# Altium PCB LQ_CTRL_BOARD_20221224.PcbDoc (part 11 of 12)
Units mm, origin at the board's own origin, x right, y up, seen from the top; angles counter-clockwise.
Board outline 260 x 142 mm, 6 copper layers (Top Layer, Mid-Layer 1, Mid-Layer 2, Mid-Layer 3, Mid-Layer 4, Bottom Layer); 1105 components, 1039 nets, 3898 pads, 1277 vias.
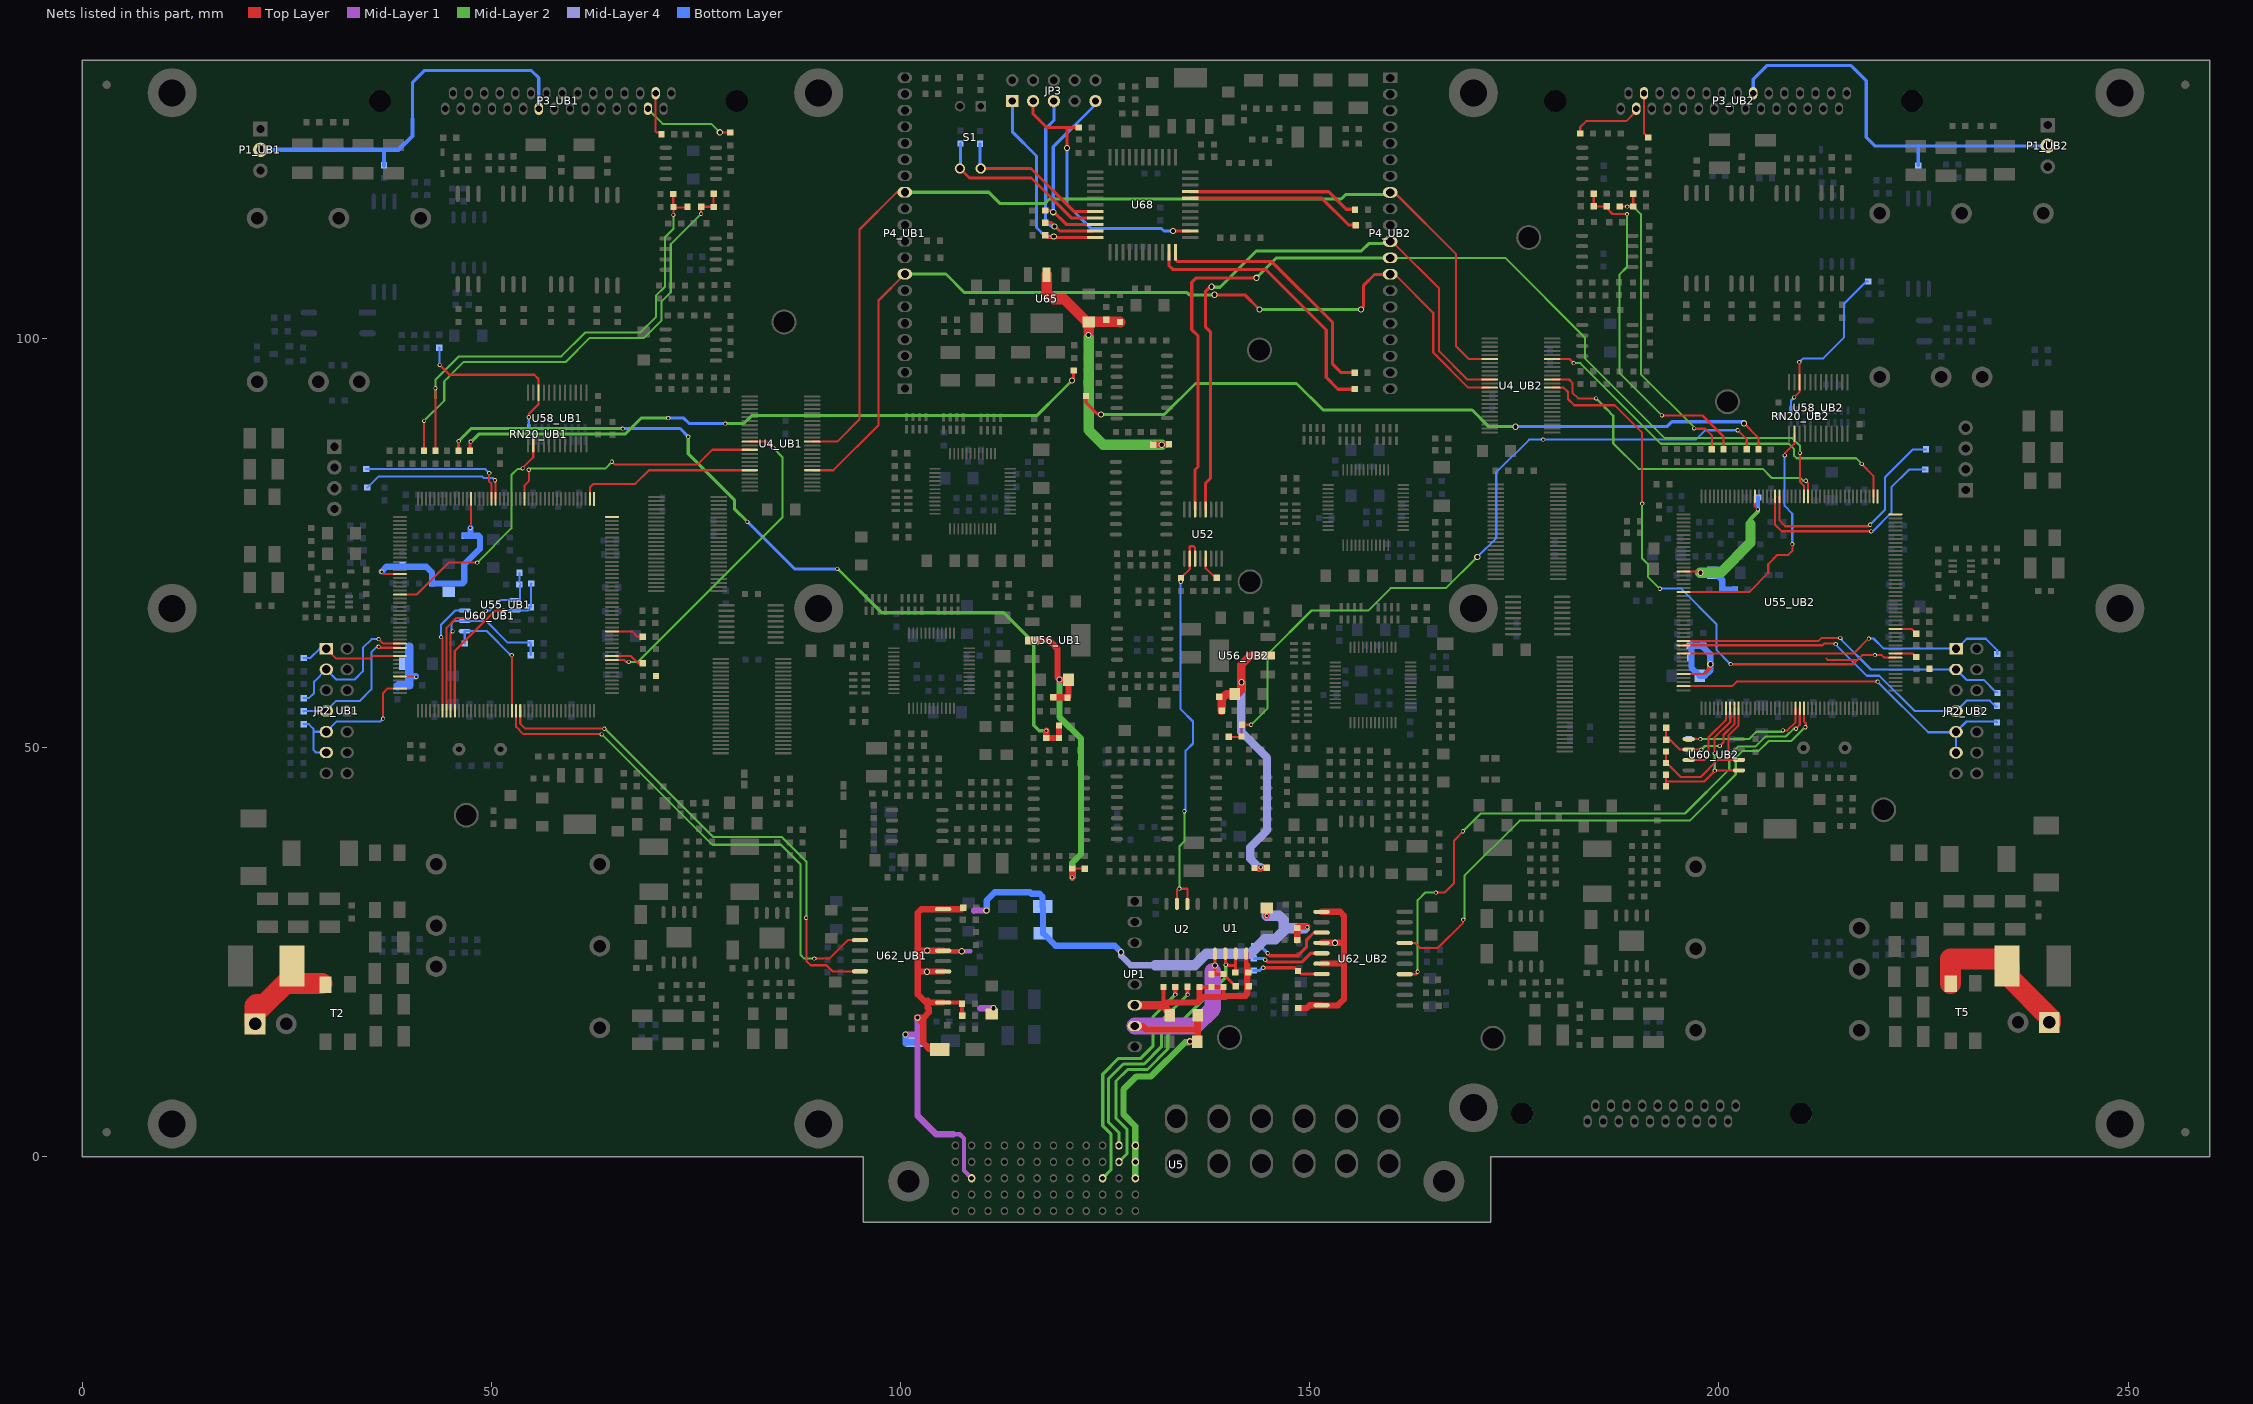
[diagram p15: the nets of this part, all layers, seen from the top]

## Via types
v1: diameter 0.508, hole 0.305, Top Layer to Bottom Layer, 845 vias
v2: diameter 0.762, hole 0.508, Top Layer to Bottom Layer, 317 vias
v3: diameter 1.27, hole 0.762, Top Layer to Bottom Layer, 77 vias
v4: diameter 2.032, hole 1.524, Top Layer to Bottom Layer, 15 vias
v5: diameter 2.032, hole 1.27, Top Layer to Bottom Layer, 11 vias
v6: diameter 1.27, hole 0.711, Top Layer to Bottom Layer, 8 vias
v7: diameter 2.54, hole 1.778, Top Layer to Bottom Layer, 3 vias
v8: diameter 1.524, hole 1.016, Top Layer to Bottom Layer, 1 vias

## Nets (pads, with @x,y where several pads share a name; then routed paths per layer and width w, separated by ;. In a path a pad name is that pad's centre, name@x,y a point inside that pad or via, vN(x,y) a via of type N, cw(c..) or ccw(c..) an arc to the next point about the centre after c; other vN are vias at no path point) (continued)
RS422_B_UB2: R366_UB2.1 R422.2 U62_UB2.17 | length 8.9
  Top Layer w0.381: v1(144.323,23.089) 148.172,23.089 R366_UB2.1@148.579,22.682 148.934,22.327 U62_UB2.17@151.455,22.327
  Bottom Layer w0.381: R422.2@143.154,22.758 143.916,22.758 144.323,23.165 v1(144.323,23.089)
RS422_GND_UB1: C420_UB1.2 C420_UB2.2 C421_UB1.2 C421_UB2.2 C422_UB1.2 C422_UB2.2 DR5.1 DR6.1 DR7.1 DR8.1 R365_UB1.1 R365_UB2.1 U5.C2 U62_UB1.11 U62_UB1.14 U62_UB1.16 U62_UB1.20 U62_UB2.11 U62_UB2.14 U62_UB2.16 U62_UB2.20 | length 160.3
  Top Layer w0.381: U62_UB1.16@105.276,25.108 v2(107.493,25.108)
  Top Layer w0.508: U62_UB1.11@105.212,18.847 107.366,18.847 C422_UB1.2@107.518,18.694 C421_UB1.2@107.518,17.221
  Top Layer w0.762: 102.337,22.631 U62_UB1.14@105.212,22.631 ; 102.514,25.171 U62_UB1.16@105.212,25.171 ; 103.238,13.475 102.819,13.894 ; DR7.1@104.8,13.106 103.607,13.106 102.819,13.894 ; U62_UB1.11@105.212,18.847 103.53,18.847 103.327,19.05 103.327,18.618 ; R365_UB1.1@107.676,30.429 107.498,30.251 U62_UB1.20@105.212,30.251 102.54,30.251 102.108,29.82 102.108,19.837 103.327,18.618 ; v2(111.379,18.136) 111.379,17.17 C420_UB1.2@111.392,17.183 ; v1(144.729,29.439) C420_UB2.2@144.729,30.404 ; C422_UB2.2@148.488,26.354 C422_UB2.2@148.488,26.492 C421_UB2.2@148.488,27.936 148.488,28.042 148.59,28.143 v1@149.708,28.143 ; R365_UB2.1@148.604,18.161 149.657,18.161 150.012,18.517 U62_UB2.20@151.455,18.517 151.48,18.491 153.416,18.491 154.178,19.253 154.178,23.571 ; U62_UB2.16@151.455,23.597 154.153,23.597 154.178,23.571 ; U62_UB2.14@151.455,26.137 v2(153.086,26.137) ; U62_UB2.11@151.455,29.921 153.721,29.921 154.178,29.464 154.178,26.238 ; v2@153.111,26.137 v2(153.086,26.137) ; 102.819,13.894 102.819,16.993 ; 102.819,13.894 102.794,13.919 102.794,16.231 102.032,16.993 v2(102.083,16.993) 102.819,16.993 ; 102.819,16.993 103.454,17.628 103.454,18.085 103.327,18.212 103.327,18.618 ; v2(153.086,26.137) 154.076,26.137 154.178,26.238 ; 154.178,23.571 154.178,26.238
  Mid-Layer 1 w0.508: 105.054,25.019 105.131,25.095 107.48,25.095 v2(107.493,25.108) 108.547,25.108 108.56,25.121 ; 106.451,2.743 107.239,2.743 107.772,2.21 107.772,-1.699 U5.C2@108.7,-2.627
  Mid-Layer 1 w0.762: v2(100.609,14.935) 101.956,14.935 ; 102.032,13.665 102.083,13.716 ; v2@102.032,16.993 v2@102.083,16.942 ; v2(102.083,16.993) v2@102.083,16.942 ; 106.451,2.743 104.343,2.743 102.083,5.004 102.083,13.716 ; 108.991,30.048 109.042,30.099 v2(110.49,30.099) ; 109.753,18.11 109.779,18.136 v2(111.379,18.136) ; 102.083,13.716 v2@102.083,16.942
  Mid-Layer 4 w0.762: v2(126.949,24.994) 126.949,24.562 128.118,23.393 131.14,23.393
  Mid-Layer 4 w1.27: 131.14,23.393 135.941,23.393 137.338,24.79 142.748,24.79 144.526,26.568 145.796,26.568 146.812,27.584 146.812,27.936 ; v1(144.729,29.439) 146.253,29.439 146.812,28.88 146.812,27.936 ; 149.377,27.936 146.812,27.936
  Bottom Layer w0.762: v2(100.609,14.935) 100.609,13.843 100.762,13.995 DR5.1@101.803,13.995 ; v2@110.541,30.099 110.541,31.318 111.531,32.309 115.824,32.309 116.002,32.131 116.992,32.131 117.348,31.775 117.348,30.607 DR6.1@117.373,30.582 117.424,30.531 DR8.1@117.424,27.305 118.948,25.781 126.187,25.781 v2@127,24.968
  other v1: 149.733,28.042
  other v2: 103.226,22.606 103.276,25.197
RS422_Y_UB2: R424.2 U62_UB2.13 | length 10.2
  Top Layer w0.381: v1@144.856,24.79 145.085,24.562 148.539,24.562 149.631,25.654 149.631,26.518 150.52,27.407 U62_UB2.13@151.455,27.407
  Bottom Layer w0.381: R424.2@143.205,25.73 143.993,25.73 v1@144.755,24.968
  other v1: 144.856,24.867
RS422_Z_UB2: R423.2 U62_UB2.15 | length 8.8
  Top Layer w0.381: v1(144.577,24.054) 144.831,23.8 149.073,23.8 149.327,24.054 150.139,24.867 U62_UB2.15@151.455,24.867
  Bottom Layer w0.381: R423.2@143.18,24.232 v1@144.577,24.232
S_EXT_IO_IN1: R432.2 U68.22 | length 31.6
  Top Layer w0.381: U68.22@133.6,110.52 133.6,109.631 133.858,109.372 145.364,109.372 152.806,101.93 152.806,96.85 153.848,95.809 155.27,95.809 R432.2@155.499,95.58
S_EXT_IO_IN2: R433.2 U68.21 | length 33.7
  Top Layer w0.381: U68.21@132.8,110.52 132.8,108.907 133.274,108.433 144.602,108.433 152.019,101.016 152.019,95.225 153.467,93.777 R433.2@155.245,93.777
S_EXT_IO_OUT1: R434.2 U68.30 | length 21.1
  Top Layer w0.381: U68.30@135.4,117.907 152.298,117.907 152.311,117.919 154.457,115.773 155.346,115.773 R434.2@155.55,115.57
S_EXT_IO_OUT2: R436.2 U68.29 | length 21.7
  Top Layer w0.381: U68.29@135.4,117.12 151.485,117.12 154.762,113.843 155.397,113.843 R436.2@155.626,113.614
S_SYN_CLK: P4_UB2.11 U4_UB2.11 U52.4 | length 76.4
  Top Layer w0.254: P4_UB2.11@159.842,111.572 160.335,111.572 165.811,106.096 165.811,98.425 169.262,94.974 U4_UB2.11@172.72,94.974
  Top Layer w0.381: U52.4@137.293,79.087 137.293,82.327 137.897,82.931 137.897,100.762 137.293,101.366 137.293,105.771 137.77,106.248 v2@138.024,106.248
  Mid-Layer 2 w0.381: v2(138.024,106.299) 138.074,106.248 139.04,106.248 143.459,110.668 156.312,110.668 157.216,111.572 P4_UB2.11@159.842,111.572
S_SYN_CLKIN: P4_UB2.12 U52.6 U55_UB2.19 | length 121.4
  Top Layer w0.254: v2@143.434,107.315 v2(143.51,107.391) ; P4_UB2.12@159.635,109.572 P4_UB2.12@159.842,109.572 ; v1(209.906,86.004) 209.911,85.999 209.911,82.468 210.385,81.994 U55_UB2.19@210.385,80.696
  Top Layer w0.381: U52.6@135.993,79.087 135.993,83.923 136.347,84.277 136.347,100.305 135.585,101.067 135.585,106.858 136.119,107.391 143.358,107.391 v2@143.434,107.315
  Mid-Layer 2 w0.254: P4_UB2.12@159.585,109.83 173.888,109.83 183.617,100.101 183.617,97.561 193.37,87.808 208.966,87.808 209.911,86.863 209.911,86.007 209.908,86.004 v1(209.906,86.004)
  Mid-Layer 2 w0.381: v2(143.51,107.391) 145.948,109.83 P4_UB2.12@159.585,109.83
S_SYNC_CLK: R6.1 U52.13 | length 3
  Top Layer w0.254: U52.13@137.293,73.087 137.293,71.902 138.455,70.739 R6.1@138.659,70.739
SCI_RXDA_UB1: U4_UB1.36 U55_UB1.141 | length 40.4
  Top Layer w0.254: U55_UB1.141@64.74,60.691 66.258,60.691 66.497,60.452 v1(66.802,60.452) ; U4_UB1.36@81.585,87.382 83.687,87.382 v1(84.455,86.614)
  Mid-Layer 2 w0.254: v1(66.802,60.452) 67.92,60.452 85.573,78.105 85.573,85.496 v1(84.455,86.614)
SCI_RXDA_UB2: U4_UB2.36 U55_UB2.141 | length 72.7
  Top Layer w0.254: U4_UB2.36@179.629,93.974 180.981,93.974 181.077,93.878 181.127,93.878 181.559,93.447 181.559,92.583 182.321,91.821 187.257,91.821 190.627,88.451 v1(190.627,79.807) ; v1@201.422,60.173 216.398,60.173 216.916,60.691 ; 213.157,60.858 213.324,60.691 216.916,60.691 ; U55_UB2.141@221.585,60.996 220.208,60.996 219.913,61.29 v1(219.075,61.29) 217.515,61.29 216.916,60.691
  Mid-Layer 2 w0.254: v1(190.627,79.807) 190.627,73.101 191.364,72.365 191.364,70.815 v1(192.786,69.393)
  Bottom Layer w0.254: v1(192.786,69.393) 192.786,69.418 192.811,69.444 195.351,69.444 199.695,65.1 199.695,61.925 v1(201.422,60.198)
SCI_TXDA_UB1: U4_UB1.43 U55_UB1.2 | length 22.5
  Top Layer w0.254: U55_UB1.2@62.04,80.391 62.04,81.776 62.484,82.22 67.615,82.22 69.277,83.882 U4_UB1.43@82.321,83.882
SCI_TXDA_UB2: U4_UB2.43 U55_UB2.2 | length 48.2
  Top Layer w0.254: U4_UB2.43@179.629,97.474 181.748,97.474 v1(182.245,96.977) ; v1@217.424,84.658 218.885,83.197 U55_UB2.2@218.885,80.696
  Mid-Layer 2 w0.254: v1(182.245,96.977) 183.058,96.977 192.913,87.122 208.534,87.122 209.194,86.462 209.194,85.649 209.499,85.344 216.764,85.344 v1(217.449,84.658)
SCIRXDA_UB1: P4_UB1.13 P4_UB2.8 U4_UB1.13 U4_UB2.6 | length 125.7
  Top Layer w0.254: U4_UB1.13@89.205,87.382 92.258,87.382 94.996,90.119 94.996,113.295 99.554,117.853 P4_UB1.13@100.533,117.853 ; P4_UB2.8@159.842,117.572 160.609,117.572 167.869,110.312 167.869,99.06 169.454,97.474 U4_UB2.6@172.72,97.474
  Mid-Layer 2 w0.381: P4_UB1.13@100.533,117.853 110.798,117.853 112.192,116.459 117.653,116.459 118.212,117.018 153.848,117.018 154.402,117.572 P4_UB2.8@159.842,117.572
SCIRXDA_UB2: P4_UB1.8 P4_UB2.13 U4_UB1.6 U4_UB2.13 | length 115.7
  Top Layer w0.254: U4_UB1.6@89.205,83.882 91.806,83.882 97.307,89.383 97.307,104.627 P4_UB1.8@100.533,107.853 ; P4_UB2.13@159.842,107.572 160.627,107.572 165.1,103.099 165.1,98.273 169.398,93.974 U4_UB2.13@172.009,93.974
  Top Layer w0.381: v2@138.379,105.308 142.088,105.308 v2(143.866,103.53) ; 156.591,103.835 156.591,106.477 157.912,107.798 159.617,107.798 P4_UB2.13@159.842,107.572
  Mid-Layer 2 w0.381: P4_UB1.8@100.533,107.853 105.558,107.853 107.823,105.588 135.026,105.588 135.306,105.308 135.509,105.308 138.354,105.308 v2(138.379,105.334) ; v2(143.866,103.53) v2(156.286,103.53) 155.524,103.53
SCIRXDB_UB1: R29_UB1.1 U55_UB1.26 | length 18.5
  Top Layer w0.254: v1(49.759,83.541) 49.714,83.496 49.714,82.53 50.04,82.204 U55_UB1.26@50.04,80.391
  Bottom Layer w0.254: R29_UB1.1@34.722,84.023 47.396,84.023 49.276,84.023 v1(49.759,83.541)
SCIRXDB_UB2: R29_UB2.1 U55_UB2.26 | length 27.2
  Top Layer w0.254: U55_UB2.26@206.885,80.696 206.844,80.654 206.844,77.255 207.67,76.429 218.567,76.429 v1(218.592,76.403)
  Bottom Layer w0.254: v1(218.592,76.403) 218.794,76.403 221.082,78.691 221.082,81.813 223.241,83.972 224.003,83.972 R29_UB2.1@225.222,83.972
SCIRXDC_UB1: U55_UB1.113 U62_UB1.4 | length 63.1
  Top Layer w0.254: U55_UB1.113@53.04,54.491 53.04,52.522 53.924,51.638 63.449,51.638 v1(63.475,51.613) ; v1(89.459,24.206) 91.303,24.206 93.563,26.467 U62_UB1.4@95.052,26.467
  Mid-Layer 2 w0.254: v1@63.5,51.638 77.013,38.125 85.395,38.125 87.782,35.738 87.782,24.689 88.265,24.206 v1(89.459,24.206)
SCIRXDC_UB2: U55_UB2.113 U62_UB2.4 | length 72.4
  Top Layer w0.254: U62_UB2.4@161.615,22.301 163.017,22.301 v1@163.246,22.53 ; v1(165.43,32.283) 166.522,32.283 167.64,33.401 167.64,38.633 168.758,39.751 v1(168.732,39.776) ; v1(209.423,52.299) 209.885,52.761 ; 209.885,53.035 209.885,52.761 ; U55_UB2.113@209.885,54.796 209.885,52.761
  Mid-Layer 2 w0.254: v1(163.195,22.606) 163.195,31.344 164.135,32.283 v1(165.43,32.283) ; v1@168.732,39.751 170.917,41.935 195.859,41.935 201.27,47.346 201.27,49.022 202.387,50.14 204.495,50.14 205.715,51.359 208.204,51.359 209.144,52.299 v1(209.423,52.299)
SCITXDB_UB1: R30_UB1.2 U55_UB1.25 | length 18.6
  Top Layer w0.254: v1(50.444,82.652) 50.54,82.556 U55_UB1.25@50.54,80.391
  Bottom Layer w0.254: R30_UB1.2@34.849,81.763 36.195,83.109 48.895,83.109 49.073,82.931 50.165,82.931 v1(50.444,82.652)
SCITXDB_UB2: R30_UB2.2 U55_UB2.25 | length 27.4
  Top Layer w0.254: U55_UB2.25@207.385,80.696 207.385,77.755 208.102,77.038 218.288,77.038 v1(218.465,77.216)
  Bottom Layer w0.254: v1(218.465,77.216) 220.294,79.045 220.294,83.007 223.698,86.411 225.273,86.411 R30_UB2.2@225.298,86.436
SCITXDC_UB1: U55_UB1.114 U62_UB1.7 | length 62.7
  Top Layer w0.254: U55_UB1.114@53.54,54.491 53.54,52.911 54.102,52.349 v1@63.83,52.349 ; v1(88.468,29.21) 88.519,29.159 88.519,23.901 89.027,23.393 90.957,23.393 91.694,22.657 U62_UB1.7@95.052,22.657
  Mid-Layer 2 w0.254: v1@63.881,52.324 77.14,39.065 85.496,39.065 88.519,36.043 v1@88.519,29.21
  other v1: 63.83,52.299
SCITXDC_UB2: U55_UB2.114 U62_UB2.7 | length 67.4
  Top Layer w0.254: U62_UB2.7@161.615,26.111 162.916,26.111 163.5,25.527 165.684,25.527 168.758,28.6 v1(168.758,28.981) ; 210.385,53.594 210.385,53.191 ; U55_UB2.114@210.385,54.796 210.385,53.191 ; v1(210.566,52.476) 210.642,52.553 210.642,52.934 210.385,53.191
  Mid-Layer 2 w0.254: v1(168.758,28.981) 168.91,29.134 168.91,34.315 175.666,41.072 196.418,41.072 202.057,46.711 202.057,48.757 202.855,49.555 204.826,49.555 206.07,50.8 208.864,50.8 210.337,52.273
SLT_MODE0: R32.1 S1.4 U68.7 | length 18.3
  Top Layer w0.381: S1.4@109.804,120.752 115.951,120.752 121.183,115.52 U68.7@122.834,115.52
  Bottom Layer w0.381: R32.1@109.703,123.774 109.703,120.853 S1.4@109.804,120.752
SLT_MODE1: R34.1 S1.3 U68.8 | length 21.1
  Top Layer w0.381: S1.3@107.264,120.752 108.433,119.583 116.002,119.583 120.865,114.72 U68.8@122.834,114.72
  Bottom Layer w0.381: S1.3@107.264,120.752 107.34,120.828 R34.1@107.34,123.8
SPICLKA_UB1: R350_UB1.1 R364_UB1.1 U55_UB1.98 U60_UB1.6 | length 21.8
  Top Layer w0.254: U55_UB1.98@45.54,54.491 45.54,61.796 50.495,66.751 v1(51.486,66.751)
  Bottom Layer w0.254: v1(51.486,66.751) U60_UB1.6@52.908,66.751 54.458,66.751 R364_UB1.1@54.839,67.132 54.839,70.002 R350_UB1.1@54.889,70.053
SPICLKA_UB2: R350_UB2.1 R364_UB2.1 U55_UB2.98 U60_UB2.6 | length 18.7
  Top Layer w0.254: R350_UB2.1@193.548,49.53 R364_UB2.1@193.548,48.108 193.65,48.108 194.742,47.015 195.351,46.406 197.764,46.406 199.847,48.489 201.153,48.489 ; U55_UB2.98@202.385,54.796 202.385,52.678 201.193,51.486 201.193,48.529 201.153,48.489 ; U60_UB2.6@202.459,48.489 201.153,48.489
SPISIMOA_UB1: R349_UB1.1 R361_UB1.1 U55_UB1.96 U60_UB1.5 | length 23.5
  Top Layer w0.254: U55_UB1.96@44.54,54.491 44.54,64.657 45.695,65.811 48.463,65.811 v1(49.352,66.7)
  Bottom Layer w0.254: v1(49.352,66.7) 49.378,66.726 49.809,66.726 51.105,68.021 U60_UB1.5@52.908,68.021 53.289,68.021 53.492,68.224 53.492,69.85 R361_UB1.1@53.594,69.952 ; R361_UB1.1@53.442,70.206 R349_UB1.1@53.442,71.349
SPISIMOA_UB2: R349_UB2.1 R361_UB2.1 U55_UB2.96 U60_UB2.5 | length 19.3
  Top Layer w0.254: R361_UB2.1@193.548,45.263 193.548,45.822 ; 193.548,45.847 193.548,45.822 ; R349_UB2.1@193.548,46.685 193.548,45.822 ; v1@199.441,49.281 199.441,51.181 201.385,53.125 U55_UB2.96@201.385,54.796 ; U60_UB2.5@202.459,47.219 199.593,47.219 198.222,45.847 193.573,45.847 193.548,45.822
  Mid-Layer 2 w0.254: v1(199.492,47.193) v1@199.492,49.251
  other v1: 199.492,49.276
SPISOMIA_UB1: R348_UB1.1 R363_UB1.1 U55_UB1.97 U60_UB1.2 | length 22.7
  Top Layer w0.254: U55_UB1.97@45.04,54.491 45.04,63.963
  Bottom Layer w0.254: v1@45.161,64.313 45.161,65.176 45.466,65.481 U60_UB1.2@46.761,65.481 49.352,65.481 52.019,62.814 R348_UB1.1@54.813,62.814 ; R363_UB1.1@54.813,61.29 54.825,61.302 R348_UB1.1@54.825,62.738
  other v1: 45.263,64.186
SPISOMIA_UB2: R348_UB2.1 R363_UB2.1 U55_UB2.97 U60_UB2.2 | length 14
  Top Layer w0.254: R348_UB2.1@193.564,52.426 R363_UB2.1@193.564,50.952 194.031,50.952 195.224,49.759 U60_UB2.2@196.312,49.759 197.815,49.759 v1(197.841,49.733) ; v1(200.101,50.19) 200.558,50.648 200.558,51.537 201.885,52.863 U55_UB2.97@201.885,54.796
  Mid-Layer 2 w0.254: v1(197.841,49.733) 198.298,50.19 v1(200.101,50.19)
SPISTEA_UB1: R362_UB1.1 U55_UB1.112 U60_UB1.1 | length 15.2
  Top Layer w0.254: U55_UB1.112@52.54,54.491 v1@52.54,61.226
  Bottom Layer w0.254: R362_UB1.1@46.761,62.713 U60_UB1.1@46.761,64.211 46.787,64.237 49.442,64.237 52.389,61.29 v1(52.502,61.29)
SPISTEA_UB2: R362_UB2.1 U55_UB2.112 U60_UB2.1 | length 17
  Top Layer w0.254: U60_UB2.1@196.312,51.029 v1(197.739,51.029) ; v1(207.823,52.095) 208.369,52.095 209.385,53.111 ; 209.385,53.162 U55_UB2.112@209.385,54.796
  Mid-Layer 2 w0.254: v1(197.739,51.029) 203.683,51.029 204.583,51.929 207.657,51.929 v1(207.823,52.095)
  Bottom Layer w0.254: R362_UB2.1@196.312,51.029 v1(197.739,51.029)
SYN_CLKOUT_UB1: U4_UB1.38 U55_UB1.18 | length 32.1
  Top Layer w0.254: U55_UB1.18@54.04,80.391 54.04,82.006 54.585,82.55 v1@54.585,84.074 ; v1(64.74,84.912) 65.045,84.607 75.235,84.607 77.009,86.382 U4_UB1.38@81.585,86.382
  Mid-Layer 2 w0.254: v1@54.585,84.074 63.932,84.074 v1@64.755,84.897
  other v1: 54.585,83.947
SYN_CLKOUT_UB2: U4_UB2.38 U55_UB2.18 | length 42
  Top Layer w0.254: U4_UB2.38@179.629,94.974 181.682,94.974 182.093,94.564 182.093,93.37 182.804,92.659 v1(184.988,92.659) ; v1@210.686,82.492 210.885,82.292 U55_UB2.18@210.885,80.696
  Mid-Layer 2 w0.254: v1(184.988,92.659) 186.284,91.364 ; 186.055,91.516 186.08,91.516 ; v1(210.642,82.601) 210.287,82.601 209.956,82.931 206.479,82.931 205.361,84.049 190.195,84.049 187.096,87.147 187.096,90.526 ; 186.284,91.364 186.284,91.313 187.046,90.551 187.046,90.576 187.096,90.526 ; 186.284,91.364 187.096,90.551 187.096,90.526
SYNC_CLKIN: R5.1 U2.6 U2.7 U52.10 U52.11 | length 51
  Top Layer w0.254: U2.7@133.782,30.886 133.782,32.614 133.909,32.741 135.026,32.741 135.052,32.766 U2.6@135.052,30.886 ; v1(134.239,70.256) 134.264,70.282 R5.1@134.264,70.714 135.343,71.792 U52.10@135.343,73.087 135.343,74.56 135.382,74.599 135.8,74.599 135.814,74.613 135.993,74.434 U52.11@135.993,73.087
  Mid-Layer 2 w0.254: v1(134.087,32.766) 134.087,37.922 134.696,38.532 ; 134.696,38.989 134.696,38.532 ; v1(134.696,42.215) 134.696,38.532
  Bottom Layer w0.254: v1(134.239,70.256) 134.239,54.686 135.738,53.188 135.738,50.495 134.849,49.606 v1@134.849,42.215
SYNC_CLKIN1: R13.1 U5.C10 | length 29.5
  Top Layer w0.508: v1(133.579,19.812) R13.1@133.579,20.752
  Mid-Layer 2 w0.381: U5.C10@124.7,-2.627 125.705,-1.623 125.705,2.794 124.714,3.785 124.714,10.084 126.644,12.014 129.362,12.014 130.835,13.487 130.835,17.069 v1(133.579,19.812)
SYNC_CLKIN2: R11.1 U5.E11 | length 25.7
  Top Layer w0.508: v1(135.077,19.812) R11.1@135.077,20.777
  Mid-Layer 2 w0.381: U5.E11@126.492,1.581 U5.E11@126.7,1.373 126.7,2.942 125.425,4.216 125.425,9.525 127.229,11.328 129.769,11.328 131.877,13.437 131.877,16.612 v1(135.077,19.812)
SYNC_GND: C5.1 C6.2 C7.1 C8.1 C9.1 U1.5 U5.C12 U5.D12 U5.E12 UP1.7 | length 56.7
  Top Layer w0.381: C7.1@137.998,22.301 138.405,22.301 ; U1.5@138.43,24.816 v2(138.43,23.368) 138.43,22.327 138.405,22.301 ; C9.1@139.471,22.327 C9.1@139.446,22.301 ; C8.1@140.97,20.828 140.945,20.828 139.471,22.301 C9.1@139.446,22.301 ; 138.405,22.301 C9.1@139.446,22.301
  Top Layer w0.762: UP1.7@128.626,15.977 129.616,15.977 130.048,15.545 136.322,15.545 ; v2(135.357,14.097) 135.407,14.046 C5.1@136.271,14.046 136.322,14.097 136.322,15.545 ; 136.246,16.002 136.246,17.297 136.322,17.374 C6.2@136.322,17.653 ; C6.2@136.322,17.297 136.322,15.545
  Mid-Layer 1 w2.032: UP1.7@128.626,15.977 136.017,15.977 138.176,18.136 138.176,22.682
  Mid-Layer 2 w0.762: U5.C12@128.7,-2.627 U5.D12@128.7,-0.627 U5.E12@128.7,1.373 128.7,3.736 127.254,5.182 127.254,8.23 128.829,9.804 130.607,9.804 134.798,13.995 v2@135.255,13.995
SYNC_OUT: R12.2 U1.6 U1.7 U5.D11 | length 39
  Top Layer w0.381: U1.6@139.7,24.816 139.7,23.774 ; R12.2@140.919,22.504 140.919,23.368 ; U1.7@140.97,24.816 140.919,24.765 140.919,23.368 ; 139.7,23.774 139.7,23.495 v1(139.751,23.444) 139.827,23.368 140.106,23.368 ; 139.7,23.774 140.106,23.368 ; 140.106,23.368 140.919,23.368
  Mid-Layer 2 w0.381: U5.D11@126.7,-0.627 127.66,0.333 127.66,3.383 126.34,4.704 126.34,9.246 127.762,10.668 130.175,10.668 132.664,13.157 132.664,14.859 139.725,21.92 ; 139.725,21.92 139.725,23.419 v1(139.751,23.444) 139.751,21.946 139.725,21.92
SYNC_VCC: C6.1 C7.2 C8.2 C9.2 R10.1 R12.1 R14.1 U1.8 UP1.6 | length 33.1
  Top Layer w0.508: 132.029,18.517 132.131,18.415 R10.1@132.131,20.752 ; R14.1@136.55,20.752 C9.2@139.471,20.752 139.471,19.787 139.624,19.634 ; 141.91,19.533 142.215,19.533 142.545,19.863 C8.2@142.545,20.828 142.545,23.393 142.24,23.698 ; 142.011,19.634 142.24,19.863 142.24,23.698 ; U1.8@142.24,24.816 142.24,23.698
  Top Layer w0.762: 132.131,18.415 132.563,18.847 136.246,18.847 136.55,19.152 ; R14.1@136.55,20.752 136.55,19.152 ; 139.624,19.634 142.011,19.634 ; 139.725,19.533 136.931,19.533 136.55,19.152
  Top Layer w1.016: UP1.6@128.626,18.517 132.029,18.517 ; 132.131,18.415 C6.1@132.893,17.653
TCK1: JP3.1 R35.2 U68.11 | length 24.5
  Top Layer w0.381: R35.2@117.704,112.598 117.982,112.32 U68.11@122.834,112.32
  Bottom Layer w0.381: JP3.1@113.665,129 113.665,125.222 116.611,122.276 116.611,113.538 117.704,112.446 v2(118.72,112.446)
TCK_UB1: JP2_UB1.9 JP2_UB1.11 R309_UB1.2 U55_UB1.87 | length 20.3
  Top Layer w0.254: v1(36.779,53.543) 36.779,56.667 37.303,57.191 U55_UB1.87@38.84,57.191
  Bottom Layer w0.254: R309_UB1.2@27.076,52.857 27.711,52.857 28.27,52.299 28.27,51.968 ; JP2_UB1.11@29.845,49.389 28.589,49.389 28.27,49.708 28.27,51.968 ; v1(36.779,53.543) 36.398,53.162 31.078,53.162 JP2_UB1.9@29.845,51.929 28.309,51.929 28.27,51.968
TCK_UB2: JP2_UB2.9 JP2_UB2.11 R309_UB2.2 U55_UB2.87 | length 44
  Top Layer w0.254: U55_UB2.87@195.685,57.496 201.615,57.496 202.178,58.059 v1(219.386,58.059)
  Bottom Layer w0.254: v1(219.386,58.059) 225.577,51.867 228.676,51.867 228.981,51.562 JP2_UB2.11@228.981,49.378 ; JP2_UB2.9@228.981,51.918 230.251,53.188 233.87,53.188 R309_UB2.2@233.985,53.072
TDI1: JP3.9 R38.2 U68.9 | length 22.5
  Top Layer w0.381: R38.2@117.678,115.621 118.542,115.621 120.243,113.92 U68.9@123.8,113.92
  Bottom Layer w0.381: v2(118.669,115.418) 118.669,123.419 123.825,128.575 JP3.9@123.825,129
TDI_UB1: JP2_UB1.3 R306_UB1.2 U55_UB1.76 | length 18.5
  Top Layer w0.254: v1@36.233,63.259 36.801,62.691 U55_UB1.76@38.84,62.691
  Bottom Layer w0.254: R306_UB1.2@27.076,56.032 27.711,56.032 28.346,56.667 28.346,58.051 JP2_UB1.3@29.845,59.549 31.076,58.318 33.325,58.318 34.315,59.309 34.315,62.179 35.382,63.246 v1(36.22,63.246)
TDI_UB2: JP2_UB2.3 R306_UB2.2 U55_UB2.76 | length 41.3
  Top Layer w0.254: U55_UB2.76@195.685,62.996 212.145,62.996 212.547,63.398 v1(214.833,63.398)
  Bottom Layer w0.254: v1(214.833,63.398) 215.011,63.221 215.011,63.119 218.592,59.538 JP2_UB2.3@228.981,59.538 230.251,58.268 232.359,58.268 233.858,56.769 R306_UB2.2@234.041,56.769
TDO1: JP3.3 R36.2 U68.24 | length 33.7
  Top Layer w0.381: JP3.3@116.205,129 116.205,127.406 117.856,125.755 120.244,125.755 ; 120.269,125.755 120.244,125.755 ; v2(120.345,123.266) 120.345,125.654 120.244,125.755 ; R36.2@121.793,125.755 120.244,125.755 ; v2(133.299,113.106) 133.313,113.12 U68.24@135.4,113.12
  Bottom Layer w0.381: v2(120.345,123.266) 120.345,116.357 123.292,113.411 131.902,113.411 132.207,113.106 v2(133.299,113.106)
TDO_UB1: JP2_UB1.7 R307_UB1.2 U55_UB1.77 | length 17.8
  Top Layer w0.254: v1@36.068,62.357 36.234,62.191 U55_UB1.77@38.84,62.191
  Bottom Layer w0.254: R307_UB1.2@27.076,54.432 R307_UB1.2@27.114,54.469 ; R307_UB1.2@27.076,54.469 R307_UB1.2@27.114,54.469 ; v1@36.068,62.357 35.357,61.646 35.357,57.099 33.96,55.702 31.078,55.702 JP2_UB1.7@29.845,54.469 R307_UB1.2@27.114,54.469
  other v1: 36.22,62.332
TDO_UB2: JP2_UB2.7 R307_UB2.2 U55_UB2.77 | length 42.7
  Top Layer w0.254: U55_UB2.77@195.685,62.496 212.661,62.496 212.877,62.713 214.198,62.713 v1(214.274,62.636)
  Bottom Layer w0.254: v1(214.274,62.636) 214.274,62.56 214.3,62.56 218.084,58.776 219.608,58.776 223.926,54.458 JP2_UB2.7@228.981,54.458 230.251,55.728 233.096,55.728 233.795,55.028 R307_UB2.2@233.985,55.028
TEMP_A1_UB1: C397_UB1.1 R3_UB1.2 R338_UB1.2 R341_UB1.2 | length 100.8
  Top Layer w0.381: R3_UB1.2@45.999,86.258 45.999,87.427 v1(46.025,87.452)
  Top Layer w0.762: v1(117.831,52.07) 117.825,52.065 R338_UB1.2@117.825,51.181 117.851,51.156 R341_UB1.2@119.355,51.156 C397_UB1.1@119.355,52.68
  Mid-Layer 2 w0.381: v1(46.025,87.452) 47.549,88.976 v1(66.04,88.976) ; v1(74.066,87.986) 74.066,85.903 79.705,80.264 79.705,79.172 v1(81.305,77.572) ; v1(92.304,71.831) 92.304,71.882 97.714,66.472 112.598,66.472 116.281,62.789 116.281,52.705 116.942,52.045 117.805,52.045 v1(117.831,52.07) v1@117.843,52.083
  Bottom Layer w0.381: v1(66.04,88.976) 73.076,88.976 v1(74.066,87.986) ; v1(81.305,77.572) 87.046,71.831 v1(92.304,71.831)
TEMP_A1_UB2: C397_UB2.1 R3_UB2.2 R338_UB2.2 R341_UB2.2 | length 90.3
  Top Layer w0.254: R338_UB2.2@140.106,51.308 141.63,51.308 R341_UB2.2@141.656,51.333 141.656,52.705 C397_UB2.1@141.732,52.781 v1(142.85,52.781) ; v1(202.288,88.773) 203.403,87.658 R3_UB2.2@203.403,86.436
  Mid-Layer 2 w0.254: v1(142.85,52.781) 144.831,54.762 144.831,61.341 150.228,66.739 157.137,66.739 157.15,66.726 159.893,69.469 ; 160.35,69.469 159.893,69.469 ; v2(170.485,73.279) 170.459,73.279 166.649,69.469 159.893,69.469
  Bottom Layer w0.254: v2(170.485,73.279) 172.796,75.59 172.796,83.617 176.809,87.63 v1(178.511,87.63) 197.18,87.63 198.323,88.773 v1(202.288,88.773)
TEMP_B1: R4_UB1.2 R374.2 | length 80.8
  Top Layer w0.381: R4_UB1.2@47.396,86.258 47.396,87.224 47.549,87.376 v1(47.473,87.376) ; v2(120.955,94.844) 121.158,95.047 R374.2@121.158,96.063
  Mid-Layer 2 w0.381: v1(47.473,87.376) 47.549,87.376 48.463,88.29 66.345,88.29 68.301,90.246 v1(71.628,90.246) ; v1(78.613,89.586) 80.848,89.586 81.813,90.551 116.662,90.551 119.672,93.561 ; 120.472,94.361 119.672,93.561 ; v2(120.955,94.844) 119.672,93.561
  Bottom Layer w0.381: v1(71.628,90.246) 73.533,90.246 74.193,89.586 v1(78.613,89.586)
TEMP_B1_UB2: R4_UB2.2 R378.2 | length 89.8
  Top Layer w0.254: v2(203.073,89.611) 204.826,87.859 R4_UB2.2@204.826,86.436
  Top Layer w0.381: R378.2@122.682,92.964 122.682,92.126 124.054,90.754 v2@124.511,90.754
  Mid-Layer 2 w0.381: v2(124.485,90.703) 132.258,90.703 136.042,94.488 148.387,94.488 151.638,91.237 169.85,91.237 171.882,89.205 v2(175.133,89.205)
  Bottom Layer w0.381: v2(175.133,89.205) 193.65,89.205 194.259,89.814 202.87,89.814 v2(203.073,89.611)
TEMP_IN_UB1: C324_UB1.2 R18_UB1.1 R285_UB1.2 R300_UB1.2 | length 59.6
  Top Layer w0.254: R300_UB1.2@43.18,86.258 v1(43.18,93.904) ; R18_UB1.1@72.238,117.526 72.238,116.007 C324_UB1.2@72.263,115.982 ; C324_UB1.2@72.263,116.053 C324_UB1.2@72.263,115.982 ; v1@72.301,115.126 72.263,115.164 C324_UB1.2@72.263,115.982 ; R285_UB1.2@73.97,116.078 73.869,115.976 72.268,115.976 C324_UB1.2@72.263,115.982
  Mid-Layer 2 w0.254: v1(43.18,93.904) 43.18,92.634 43.18,94.92 ; 43.65,95.39 43.18,94.92 ; v1(72.263,115.087) 72.263,113.386 71.222,112.344 71.222,106.299 70.104,105.181 70.104,102.591 68.224,100.711 61.493,100.711 58.572,97.79 46.05,97.79 43.18,94.92
TEMP_IN_UB2: C324_UB2.2 R18_UB2.1 R285_UB2.2 R300_UB2.2 | length 43.5
  Top Layer w0.254: R18_UB2.1@184.709,117.653 C324_UB2.2@184.709,116.129 R285_UB2.2@186.309,116.129 186.309,115.875 186.995,115.189 v1(188.773,115.189) ; v1(193.04,90.576) 197.993,90.576 200.558,88.011 R300_UB2.2@200.558,86.436
  Mid-Layer 2 w0.254: 188.773,108.737 188.773,108.712 ; v1(188.773,115.189) 188.773,108.712 ; v1(193.04,90.576) 193.04,90.602 187.833,95.809 187.833,107.772 188.773,108.712
TEMP_UB1: P3_UB1.29 R291_UB1.1 | length 5.3
  Top Layer w0.254: P3_UB1.29@70.091,129.952 70.091,125.291 70.236,125.146 R291_UB1.1@70.663,125.146
TEMP_UB2: P3_UB2.29 R291_UB2.1 | length 8.7
  Top Layer w0.254: R291_UB2.1@183.058,125.019 183.058,125.82 183.781,126.543 188.671,126.543 189.906,127.778 P3_UB2.29@189.906,128.047
TMS1: JP3.5 R37.2 U68.10 | length 22.6
  Top Layer w0.381: R37.2@117.704,114.122 118.44,114.122 119.443,113.12 U68.10@123.495,113.12
  Bottom Layer w0.381: JP3.5@118.745,129 118.745,126.619 117.754,125.628 117.754,116.789 117.729,116.764 117.729,114.376 118.44,113.665 v2(118.821,113.665)
TMS_UB1: JP2_UB1.1 R303_UB1.2 U55_UB1.79 | length 12.9
  Top Layer w0.254: JP2_UB1.1@29.845,62.089 31.076,60.858 35.255,60.858 35.588,61.191 U55_UB1.79@38.84,61.191
  Bottom Layer w0.254: R303_UB1.2@27.076,60.935 27.889,60.935 29.044,62.089 JP2_UB1.1@29.845,62.089
TMS_UB2: JP2_UB2.1 R303_UB2.2 U55_UB2.79 | length 41.1
  Top Layer w0.254: U55_UB2.79@195.685,61.496 216.487,61.496 v1@218.326,63.335
  Bottom Layer w0.254: v1(218.338,63.322) 218.897,63.322 220.142,62.078 JP2_UB2.1@228.981,62.078 229.057,62.078 230.276,63.297 232.613,63.297 234.016,61.894 R303_UB2.2@234.016,61.443
VAL_CTRL_UB1: P1_UB1.2 P3_UB1.7 R28_UB1.2 | length 48
  Bottom Layer w0.381: 40.386,126.797 40.386,131.293 41.808,132.715 54.915,132.715 55.804,131.826 P3_UB1.7@55.804,128.047
  Bottom Layer w0.508: P1_UB1.2@21.793,123.038 36.805,123.038 ; R28_UB1.2@36.906,121.158 36.906,122.936 ; 40.386,126.797 40.386,124.739 38.684,123.038 36.906,123.038 ; 36.805,123.038 36.906,122.936 ; 36.805,123.038 36.906,123.038 ; 36.906,122.936 36.906,123.038
VAL_CTRL_UB2: P1_UB2.2 P3_UB2.7 R28_UB2.2 | length 54.1
  Bottom Layer w0.381: P3_UB2.7@204.193,129.952 204.193,131.676 205.842,133.325 ; 210.972,133.325 205.842,133.325 ; R28_UB2.2@224.358,121.107 224.358,123.52 ; 224.358,123.571 224.358,123.52 ; P1_UB2.2@240.182,123.52 224.358,123.52 ; 205.842,133.325 216.154,133.325 218.008,131.47 218.008,124.562 219.05,123.52 224.358,123.52
VALVE_CTRL_UB1: U55_UB1.64 U58_UB1.14 | length 28.6
  Top Layer w0.254: U55_UB1.64@38.84,68.691 40.865,68.691 44.767,72.593 v1(48.285,72.593) ; v1@53.854,84.176 55.126,85.447 U58_UB1.14@55.126,87.07
  Mid-Layer 2 w0.254: v1(48.285,72.593) 52.464,76.772 52.464,83.299 53.188,84.023 v1@53.823,84.023
  other v1: 53.823,84.099
VALVE_CTRL_UB2: U55_UB2.64 U58_UB2.14 | length 31.2
  Top Layer w0.254: U55_UB2.64@195.685,68.996 196.968,68.996 ; 196.977,68.986 196.968,68.996 ; v1@208.064,85.687 208.064,85.966 209.219,87.122 U58_UB2.14@209.219,88.34 ; v1(208.991,74.854) 208.991,74.041 208.483,73.533 207.67,73.533 207.162,73.533 206.032,72.403 206.032,71.895 206.032,71.336 203.692,68.996 196.968,68.996
  Bottom Layer w0.254: v1(208.051,85.7) 208.026,85.674 208.026,79.527 208.966,78.588 v1@208.966,74.854
VALVE_CTRLB_UB1: R26_UB1.1 RN20_UB1.1 U58_UB1.10 | length 21.2
  Top Layer w0.254: v1(43.688,96.749) 44.888,95.548 55.252,95.548 55.776,95.024 U58_UB1.10@55.776,93.37 55.776,91.945 54.585,90.754 v1(54.585,90.348)
  Bottom Layer w0.254: R26_UB1.1@43.643,98.857 43.688,98.811 v1(43.688,96.749) ; RN20_UB1.1@54.578,89.256 54.578,90.341 v1(54.585,90.348)
VALVE_CTRLB_UB2: R26_UB2.1 RN20_UB2.1 U58_UB2.10 | length 21.2
  Top Layer w0.254: v1(209.194,92.786) 209.869,93.461 U58_UB2.10@209.869,94.64 v1@209.869,97.104
  Bottom Layer w0.254: RN20_UB2.1@208.807,91.211 208.807,92.399 v1(209.194,92.786) ; v1(209.829,97.104) 210.287,97.561 212.75,97.561 215.265,100.076 215.265,104.191 R26_UB2.1@218.097,107.023 ; R26_UB2.1@218.161,106.959 R26_UB2.1@218.237,106.959
VCC_IN1: F1_UB1.1 P9_UB1.1 T2.3 | length 13.1
  Top Layer w2.54: P9_UB1.1@21.133,16.231 P9_UB1.1@21.133,17.475 ; T2.3@29.312,21.184 24.842,21.184 22.25,18.593 ; P9_UB1.1@21.133,17.475 21.133,18.415 21.311,18.593 22.25,18.593 ; P9_UB1.1@21.133,17.475 22.25,18.593
VCC_IN2: F1_UB2.1 P9_UB2.1 T5.3 | length 19.6
  Top Layer w2.54: T5.3@228.318,21.158 228.318,24.178 234.673,24.178 235.534,23.317 235.534,21.895 240.538,16.891 P9_UB2.1@240.538,16.408
VDC1_IN_UB1: C300_UB1.2 R17_UB1.1 R266_UB1.2 R297_UB1.2 | length 58.9
  Top Layer w0.254: R297_UB1.2@41.783,86.258 v1(41.783,89.916) ; v1(75.641,115.214) 75.647,115.22 R266_UB1.2@75.647,116.078 77.145,116.078 C300_UB1.2@77.171,116.053 R17_UB1.1@77.171,117.678
  Mid-Layer 2 w0.254: v1(41.783,89.916) 44.25,92.383 44.25,94.739 ; 44.77,95.26 44.25,94.739 ; v1(75.641,115.214) 71.933,111.506 71.933,105.613 70.79,104.47 70.79,102.159 68.682,100.051 62.052,100.051 59.131,97.13 46.64,97.13 44.25,94.739
VDC1_IN_UB2: C300_UB2.2 R17_UB2.1 R266_UB2.2 R297_UB2.2 | length 38.3
  Top Layer w0.254: R266_UB2.2@187.884,116.103 v1(188.798,116.103) C300_UB2.2@189.535,116.103 R17_UB2.1@189.535,117.653 ; v1(196.977,89.002) v1@196.977,89.129 ; v1@197.155,88.951 198.323,88.951 199.136,88.138 R297_UB2.2@199.136,86.436
  Mid-Layer 2 w0.254: v1(188.798,116.103) 189.535,116.103 190.475,115.164 190.475,95.631 196.977,89.129 v1(196.977,89.002)
VDC1_UB1: P3_UB1.14 R271_UB1.1 | length 11.5
  Top Layer w0.254: v2(77.927,125.171) 79.223,125.171 R271_UB1.1@79.375,125.324
  Mid-Layer 2 w0.254: P3_UB1.14@69.139,128.047 69.139,128.016 70.942,126.213 76.886,126.213 v2(77.927,125.171)
VDC1_UB2: P3_UB2.14 R271_UB2.1 | length 5.6
  Top Layer w0.254: P3_UB2.14@190.858,129.952 190.858,125.042 R271_UB2.1@191.364,124.536
VDD3VFLM_UB1: C10_UB1.1 C401_UB1.1 C402_UB1.1 R15_UB1.2 U55_UB1.84 | length 9
  Top Layer w0.254: U55_UB1.84@38.84,58.691 v1@40.742,58.691
  Bottom Layer w0.762: 39.98,58.649 40.03,58.699 v1@40.818,58.699
  Bottom Layer w1.016: R15_UB1.2@38.532,57.48 38.659,57.607 C10_UB1.1@39.98,57.607 39.98,58.649 C401_UB1.1@39.98,62.332
  other v1: 40.818,58.623
VDD3VFLM_UB2: C10_UB2.1 C401_UB2.1 C402_UB2.1 R15_UB2.2 U55_UB2.84 | length 14.5
  Top Layer w0.254: U55_UB2.84@195.685,58.996 198.162,58.996 198.349,59.182
  Top Layer w0.508: 198.349,59.182 198.958,59.792 v2(198.958,60.173)
  Bottom Layer w0.762: 196.647,59.766 C402_UB2.1@197.663,58.75 198.298,58.75 198.958,59.411 v2(198.958,60.173) 198.958,61.366 198.095,62.23 R15_UB2.2@198.095,62.433 196.647,62.433 196.647,60.96 196.647,59.766
VDDA_1V8M_UB1: C398_UB1.1 C399_UB1.1 C400_UB1.1 R16_UB1.2 U55_UB1.31 U55_UB1.59 | length 27.4
  Top Layer w0.254: v1(36.601,71.496) 36.906,71.191 U55_UB1.59@38.84,71.191 ; v1(47.447,76.835) 47.54,76.928 U55_UB1.31@47.54,80.391
  Bottom Layer w0.508: v1(36.601,71.496) v1@36.835,71.496
  Bottom Layer w0.762: v1(36.601,71.496) 37.191,72.085 42.062,72.085 42.748,71.399 R16_UB1.2@42.748,70.053 46.482,70.053 46.711,70.282 46.711,72.39 48.616,74.295 48.616,75.717 48.463,75.87 47.473,75.87 ; C400_UB1.1@46.761,75.87 47.473,75.87 ; v1(47.447,76.835) 47.473,76.81 47.473,75.87
VDDA_1V8M_UB2: C398_UB2.1 C399_UB2.1 C400_UB2.1 R16_UB2.2 U55_UB2.31 U55_UB2.59 | length 22.9
  Top Layer w0.254: U55_UB2.59@195.685,71.496 v2@197.485,71.496 ; U55_UB2.31@204.385,80.696 204.385,79.46 204.775,79.07 v1(204.775,79.096)
  Mid-Layer 2 w0.508: 203.86,77.297 203.86,77.927 204.775,78.842 v1(204.775,79.096)
  Mid-Layer 2 w1.27: v2(197.739,71.349) 200.206,71.349 203.86,75.003 203.86,77.297
  Bottom Layer w0.508: v1(204.775,79.096) 204.775,80.518 C399_UB2.1@204.8,80.543
  Bottom Layer w0.762: v2@197.632,71.349 v2(197.739,71.349) C398_UB2.1@199.187,71.349 ; 199.923,71.73 199.923,70.942 200.406,70.46 R16_UB2.2@200.406,69.291 200.431,69.317 C400_UB2.1@201.955,69.317
VREF_2V5_UB1: C394_UB1.1 C396_UB1.1 LED12_UB1.1 R334_UB1.1 R335_UB1.1 U56_UB1.2 | length 40.8
  Top Layer w0.254: R335_UB1.1@120.98,35.204 122.479,35.204 R334_UB1.1@122.504,35.179
  Top Layer w0.762: U56_UB1.2@116.098,63.068 118.212,63.068 119.177,62.103 119.177,58.572 119.456,58.293 C394_UB1.1@120.518,58.293 120.518,56.185 LED12_UB1.1@120.416,56.083 120.365,56.134 C396_UB1.1@118.663,56.134 ; v1(120.98,34.138) R335_UB1.1@120.98,35.204
  Mid-Layer 2 w0.762: v2(119.431,58.318) 119.431,53.721 122.072,51.079 122.072,36.996 120.98,35.904 v1(120.98,34.138)
VREF_2V5_UB2: C394_UB2.1 C396_UB2.1 LED12_UB2.1 R334_UB2.1 R335_UB2.1 U56_UB2.2 | length 38.8
  Top Layer w0.762: R335_UB2.1@143.256,35.281 144.729,35.281 R334_UB2.1@144.755,35.306
  Top Layer w1.016: LED12_UB2.1@139.268,54.487 139.268,55.956 139.852,56.54 C394_UB2.1@140.843,56.54 ; 139.827,56.49 141.072,56.49 141.63,57.048 141.63,60.082 142.788,61.239 U56_UB2.2@144.653,61.239
  Mid-Layer 4 w1.016: v2(141.656,57.982) 141.656,51.892 144.78,48.768 144.78,39.853 142.748,37.821 142.748,36.398 143.789,35.357 v1(144.018,35.357)
VREF_2V5MS: C433.1 C435.1 LED18.1 R375.1 R376.1 U65.2 | length 36.5
  Top Layer w0.762: R375.1@130.886,86.995 R376.1@132.537,86.995
  Top Layer w1.27: U65.2@117.856,107.772 117.856,105.613 118.694,104.775 119.99,104.775 122.758,102.006 C433.1@122.987,102.006 ; 122.987,100.813 C433.1@122.987,102.006 ; LED18.1@126.848,101.981 LED18.1@126.822,102.006 C433.1@122.987,102.006
  Mid-Layer 2 w1.27: v2@122.987,100.127 122.987,88.798 124.79,86.995 v2(131.928,86.995)
  other v2: 122.961,100.406
WP1_UB1: U55_UB1.95 U60_UB1.3 | length 14
  Top Layer w0.254: U55_UB1.95@44.04,54.491 v1@44.04,63.351
  Bottom Layer w0.254: v1(43.866,63.5) 43.866,65.038 45.579,66.751 U60_UB1.3@46.761,66.751
WP1_UB2: U55_UB2.95 U60_UB2.3 | length 9.3
  Top Layer w0.254: U60_UB2.3@196.312,48.489 198.252,48.489 198.73,48.966 198.73,51.257 200.885,53.413 U55_UB2.95@200.885,54.796
XA17_UB1: U55_UB1.176
XA17_UB2: U55_UB2.176
XA18_UB1: U55_UB1.1
XA18_UB2: U55_UB2.1
XCLOUT_UB1: R345_UB1.2
XCLOUT_UB2: R345_UB2.2
XR/#W_UB1: R322_UB1.1 U55_UB1.148 | length 4
  Top Layer w0.254: U55_UB1.148@64.74,64.191 67.203,64.191 67.843,63.551 R322_UB1.1@68.516,63.551
XR/#W_UB2: R322_UB2.1 U55_UB2.148 | length 2.8
  Top Layer w0.254: U55_UB2.148@221.585,64.496 223.54,64.496 R322_UB2.1@224.13,63.906
XREADY_UB1: R331_UB1.2 U55_UB1.142 | length 4.1
  Top Layer w0.254: U55_UB1.142@64.74,61.191 67.047,61.191 67.939,60.3 R331_UB1.2@68.503,60.3
XREADY_UB2: R331_UB2.2 U55_UB2.142 | length 2.7
  Top Layer w0.254: U55_UB2.142@221.585,61.496 223.695,61.496 R331_UB2.2@224.13,61.062
pads on no net: P3_UB1. P3_UB2. P7. U5. U57_UB1.5 U57_UB1.6 U57_UB1.7 U57_UB2.5 U57_UB2.6 U57_UB2.7 U64.5 U64.6 U64.7 UP1.5

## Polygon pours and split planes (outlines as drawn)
AGND_UB1 on Mid-Layer 1 "Top Layer-No Net" (solid, remove dead copper, pour order 78): 26 vertices, not listed, extent 91.239,36.119 123.218,85.877
AGND_UB1 on Mid-Layer 1 "Top Layer-No Net" (solid, remove dead copper, pour order 121): 34.849,87.325 34.9,87.274 34.9,70.917 48.59,70.917 48.743,71.069 48.489,71.323 48.489,92.151 39.04,92.151 38.837,92.354 34.9,88.417 34.9,87.224
28VGND1 on Mid-Layer 1 "Top Layer-No Net" (solid, remove dead copper, pour order 119): 18.237,40.056 18.415,39.878 18.415,12.497 44.45,12.497 44.602,12.344 44.653,12.395 44.653,38.278 44.323,38.278 42.469,40.132 42.443,40.107 18.136,40.107
RS422_GND_UB1 on Mid-Layer 1 "Top Layer-No Net" (solid, remove dead copper, pour order 117): 144.399,31.242 144.399,17.653 144.602,17.45 144.755,17.602 154.661,17.602 154.661,31.064 154.559,31.166 154.457,31.267 144.323,31.267
RS422_GND_UB1 on Mid-Layer 1 "Top Layer-No Net" (solid, remove dead copper, pour order 115): 101.56,30.836 101.56,13.665 102.017,13.208 107.072,13.208 108.088,13.208 110.12,15.24 110.199,15.319 110.199,30.81 101.636,30.81 101.611,30.836
GNDMS on Mid-Layer 1 "Top Layer-No Net" (solid, remove dead copper, pour order 114): 19 vertices, not listed, extent 132.512,37.262 141.021,86.995
AGND_UB2 on Mid-Layer 1 "Top Layer-No Net" (solid, remove dead copper, pour order 99): 29 vertices, not listed, extent 138.684,34.214 181.178,134.036
ISO_GND_UB1 on Mid-Layer 1 "Top Layer-No Net" (solid, remove dead copper, pour order 64): 21 vertices, not listed, extent 18.161,113.411 66.472,133.96
+5VA_UB1 on Mid-Layer 1 "Top Layer-No Net" (solid, remove dead copper, pour order 70): 27 vertices, not listed, extent 66.904,92.558 82.474,134.163
GND_UB1 on Mid-Layer 1 "Top Layer-No Net" (solid, remove dead copper, pour order 97): 63 vertices, not listed, extent 24.232,13.538 113.208,134.01
AGNDMS on Mid-Layer 1 "Top Layer-No Net" (solid, remove dead copper, pour order 79): 102.083,133.579 102.083,93.904 103.251,92.735 124.409,92.735 124.409,34.925 125.4,33.934 125.781,34.315 134.747,34.315 134.747,91.77 134.366,92.151 158.445,92.151 158.445,133.883 101.803,133.883
ISO_GND_UB2 on Mid-Layer 1 "Top Layer-No Net" (solid, remove dead copper, pour order 83): 32 vertices, not listed, extent 194.97,113.853 243.129,134
AGND_UB2 on Mid-Layer 1 "Top Layer-No Net" (solid, remove dead copper, pour order 87): 36 vertices, not listed, extent 181,69.012 208.61,133.985
GND_UB2 on Mid-Layer 1 "Top Layer-No Net" (solid, remove dead copper, pour order 100): 64 vertices, not listed, extent 145.166,13.767 237.317,133.72
28VGND2 on Mid-Layer 1 "Top Layer-No Net" (solid, remove dead copper, pour order 93): 220.421,42.494 220.421,12.395 220.472,12.344 220.599,12.217 243.129,12.217 243.129,42.367 243.18,42.418 243.103,42.494 220.472,42.494
AGND_UB1 on Top Layer "Top Layer-No Net" (solid, remove dead copper, pour order 122): 34.925,87.427 34.976,87.376 34.976,71.018 48.666,71.018 48.819,71.171 48.565,71.425 48.565,92.253 39.116,92.253 38.913,92.456 34.976,88.519 34.976,87.325
GND_UB2 on Top Layer "Top Layer-No Net" (solid, remove dead copper, pour order 109): 50 vertices, not listed, extent 158.979,13.462 237.261,134.01
AGND_UB1 on Top Layer "Top Layer-No Net" (solid, remove dead copper, pour order 107): 93.193,52.324 93.193,34.442 93.472,34.163 93.599,34.036 123.19,34.036 123.19,91.262 122.936,91.516 122.53,91.923 112.547,91.923 100.879,91.923 100.73,91.774 98.323,89.367 98.323,52.705 93.447,52.705 93.193,52.451
AGNDMS on Top Layer "Top Layer-No Net" (solid, remove dead copper, pour order 106): 22 vertices, not listed, extent 101.879,33.782 159.918,134.214
ISO_GND_UB1 on Top Layer "Top Layer-No Net" (solid, remove dead copper, pour order 65): 21 vertices, not listed, extent 18.136,113.309 66.446,133.858
AGND_UB1 on Top Layer "Top Layer-No Net" (solid, remove dead copper, pour order 71): 27 vertices, not listed, extent 66.777,92.38 82.347,133.985
GND_UB1 on Top Layer "Top Layer-No Net" (solid, remove dead copper, pour order 95): 63 vertices, not listed, extent 24.232,13.386 113.208,134.087
ISO_GND_UB2 on Top Layer "Top Layer-No Net" (solid, remove dead copper, pour order 82): 32 vertices, not listed, extent 194.97,113.802 243.129,133.949
AGND_UB2 on Top Layer "Top Layer-No Net" (solid, remove dead copper, pour order 86): 36 vertices, not listed, extent 180.975,69.037 208.585,134.01
GND_UB2 on Mid-Layer 2 "Top Layer-No Net" (solid, remove dead copper, pour order 101): 60 vertices, not listed, extent 144.941,13.691 236.94,133.89
ISO_+15V_UB1 on Mid-Layer 2 "Top Layer-No Net" (solid, remove dead copper, pour order 67): 21 vertices, not listed, extent 18.009,113.182 66.319,133.731
AGND_UB1 on Mid-Layer 2 "Top Layer-No Net" (solid, remove dead copper, pour order 72): 27 vertices, not listed, extent 67.005,92.456 82.575,134.061
GND_UB1 on Mid-Layer 2 "Top Layer-No Net" (solid, remove dead copper, pour order 96): 63 vertices, not listed, extent 24.232,13.462 113.208,134.036
ISO_+15V_UB2 on Mid-Layer 2 "Top Layer-No Net" (solid, remove dead copper, pour order 81): 32 vertices, not listed, extent 194.996,113.828 243.154,133.975
+1.9VD_UB2 on Mid-Layer 2 "Top Layer-No Net" (solid, remove dead copper, pour order 88): 194.437,81.89 194.869,81.458 194.869,42.748 216.941,42.748 223.241,49.047 222.86,49.428 222.86,82.017 194.793,82.017 194.742,81.966
AGND_UB2 on Mid-Layer 2 "Top Layer-No Net" (solid, remove dead copper, pour order 85): 36 vertices, not listed, extent 180.95,68.954 208.559,133.927
AGND_UB1 on Bottom Layer "Top Layer-No Net" (solid, remove dead copper, pour order 108): 92.126,52.375 92.126,34.493 92.405,34.214 92.532,34.087 122.123,34.087 122.123,91.313 121.869,91.567 121.463,91.973 111.481,91.973 99.812,91.973 99.663,91.824 97.257,89.418 97.257,52.756 92.38,52.756 92.126,52.502
28VGND1 on Bottom Layer "Top Layer-No Net" (solid, remove dead copper, pour order 120): 18.212,40.056 18.39,39.878 18.39,12.497 44.425,12.497 44.577,12.344 44.628,12.395 44.628,38.278 44.298,38.278 42.443,40.132 42.418,40.107 18.11,40.107
28VGND2 on Bottom Layer "Top Layer-No Net" (solid, remove dead copper, pour order 94): 220.472,42.52 220.472,12.421 220.523,12.37 220.65,12.243 243.18,12.243 243.18,42.393 243.23,42.443 243.154,42.52 220.523,42.52
GND_UB2 on Bottom Layer "Top Layer-No Net" (solid, remove dead copper, pour order 113): 36 vertices, not listed, extent 158.928,13.716 237.261,107.696
GNDMS on Bottom Layer "Top Layer-No Net" (solid, remove dead copper, pour order 112): 22 vertices, not listed, extent 101.981,33.655 158.598,133.883
ISO_GND_UB1 on Bottom Layer "Top Layer-No Net" (solid, remove dead copper, pour order 68): 21 vertices, not listed, extent 18.136,113.259 66.446,133.807
AGND_UB1 on Bottom Layer "Top Layer-No Net" (solid, remove dead copper, pour order 73): 27 vertices, not listed, extent 66.777,92.481 82.347,134.087
GND_UB1 on Bottom Layer "Top Layer-No Net" (solid, remove dead copper, pour order 98): 63 vertices, not listed, extent 24.232,13.208 113.208,134.087
ISO_GND_UB2 on Bottom Layer "Top Layer-No Net" (solid, remove dead copper, pour order 80): 32 vertices, not listed, extent 194.97,113.802 243.129,133.949
AGND_UB2 on Bottom Layer "Top Layer-No Net" (solid, remove dead copper, pour order 84): 36 vertices, not listed, extent 180.975,68.986 208.585,133.96
AGND_UB2 on Bottom Layer "Top Layer-No Net" (solid, remove dead copper, pour order 92): 29 vertices, not listed, extent 137.772,34.034 186.261,100.607
GNDMS on Mid-Layer 3 "Top Layer-No Net" (solid, remove dead copper, pour order 110): 28 vertices, not listed, extent 101.752,28.677 158.445,134.01
AGND_UB1 on Mid-Layer 3 "Top Layer-No Net" (solid, remove dead copper, pour order 62): 17 vertices, not listed, extent 70.866,34.214 88.214,101.905
+5V_UB2 on Mid-Layer 3 "Top Layer-No Net" (solid, remove dead copper, pour order 103): 29 vertices, not listed, extent 173.101,13.691 233.883,107.493
+5VA_UB2 on Mid-Layer 3 "Top Layer-No Net" (solid, remove dead copper, pour order 102): 24 vertices, not listed, extent 139.827,33.376 192.659,123.977
+3.3V_UB1 on Mid-Layer 3 "Top Layer-No Net" (solid, remove dead copper, pour order 76): 30 vertices, not listed, extent 69.895,13.564 119.933,93.797
AGND_UB1 on Mid-Layer 3 "Top Layer-No Net" (solid, remove dead copper, pour order 77): 26 vertices, not listed, extent 91.262,34.188 123.241,83.947
+3.3VD_UB1 on Mid-Layer 3 "Top Layer-No Net" (solid, remove dead copper, pour order 75): 30 vertices, not listed, extent 24.232,38.811 68.834,92.126
+12V_UB2 on Mid-Layer 4 "Top Layer-No Net" (solid, remove dead copper, pour order 69): 30 vertices, not listed, extent 142.342,34.417 168.123,134.061
+5V_UB1 on Mid-Layer 4 "Top Layer-No Net" (solid, remove dead copper, pour order 66): 23 vertices, not listed, extent 66.777,32.029 113.208,92.1
+12V_UB1 on Mid-Layer 4 "Top Layer-No Net" (solid, remove dead copper, pour order 63): 22 vertices, not listed, extent 66.853,18.542 121.615,91.745
CANGND_UB1 on Mid-Layer 4 "Top Layer-No Net" (solid, remove dead copper, pour order 118): 144.424,31.318 144.424,17.729 144.628,17.526 144.78,17.678 154.686,17.678 154.686,31.14 154.584,31.242 154.483,31.344 144.348,31.344
CANGND_UB1 on Mid-Layer 4 "Top Layer-No Net" (solid, remove dead copper, pour order 116): 101.752,30.937 101.752,13.767 102.21,13.31 107.264,13.31 108.28,13.31 110.312,15.342 110.391,15.421 110.391,30.912 101.829,30.912 101.803,30.937
+12VMS on Mid-Layer 4 "Top Layer-No Net" (solid, remove dead copper, pour order 111): 102.286,133.629 102.286,94.031 102.006,93.751 102.667,93.091 124.384,93.091 124.384,69.799 124.765,69.418 125.171,69.012 140.437,69.012 140.437,92.177 158.445,92.177 158.445,133.756 158.318,133.629 102.006,133.629
+3.3V_UB1 on Mid-Layer 4 "Top Layer-No Net" (solid, remove dead copper, pour order 105): 71.044,91.516 71.044,91.288 69.545,89.789 69.088,89.332 69.088,75.438 69.088,49.047 69.545,48.59 70.079,49.124 96.723,49.124 96.723,89.891 95.199,91.415 95.098,91.313 70.942,91.313
+5VA_UB1 on Mid-Layer 4 "Top Layer-No Net" (solid, remove dead copper, pour order 104): 46 vertices, not listed, extent 68.783,44.45 104.953,134.01
+3.3V_UB2 on Mid-Layer 4 "Top Layer-No Net" (solid, remove dead copper, pour order 90): 35 vertices, not listed, extent 144.922,12.852 192.725,99.882
+1.9VD_UB1 on Mid-Layer 4 "Top Layer-No Net" (solid, remove dead copper, pour order 74): 30 vertices, not listed, extent 24.155,38.811 68.758,92.126
+3.3VD_UB2 on Mid-Layer 4 "Top Layer-No Net" (solid, remove dead copper, pour order 89): 26 vertices, not listed, extent 190.398,39.599 236.931,92.583
+5VA_UB2 on Mid-Layer 4 "Top Layer-No Net" (solid, remove dead copper, pour order 91): 18 vertices, not listed, extent 180.924,93.828 197.028,134.112

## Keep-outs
Keep-Out Layer:
  lines w0.254: -0.003,3 ccw(c2.997,3) 2.997,0 104.2,0 104.2,-8.001 129.7,-8.001 129.7,-5 ; 0,3 0,130.988 cw(c3,130.988) 3,133.988 ; 3,134 256.997,134 ; 129.692,-5 163.2,-5 163.2,0 256.997,0 ccw(c256.997,3) 259.997,3 ; 256.997,134.01 cw(c256.997,131.01) 259.997,131.01 ; 260,2.972 260,131.01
